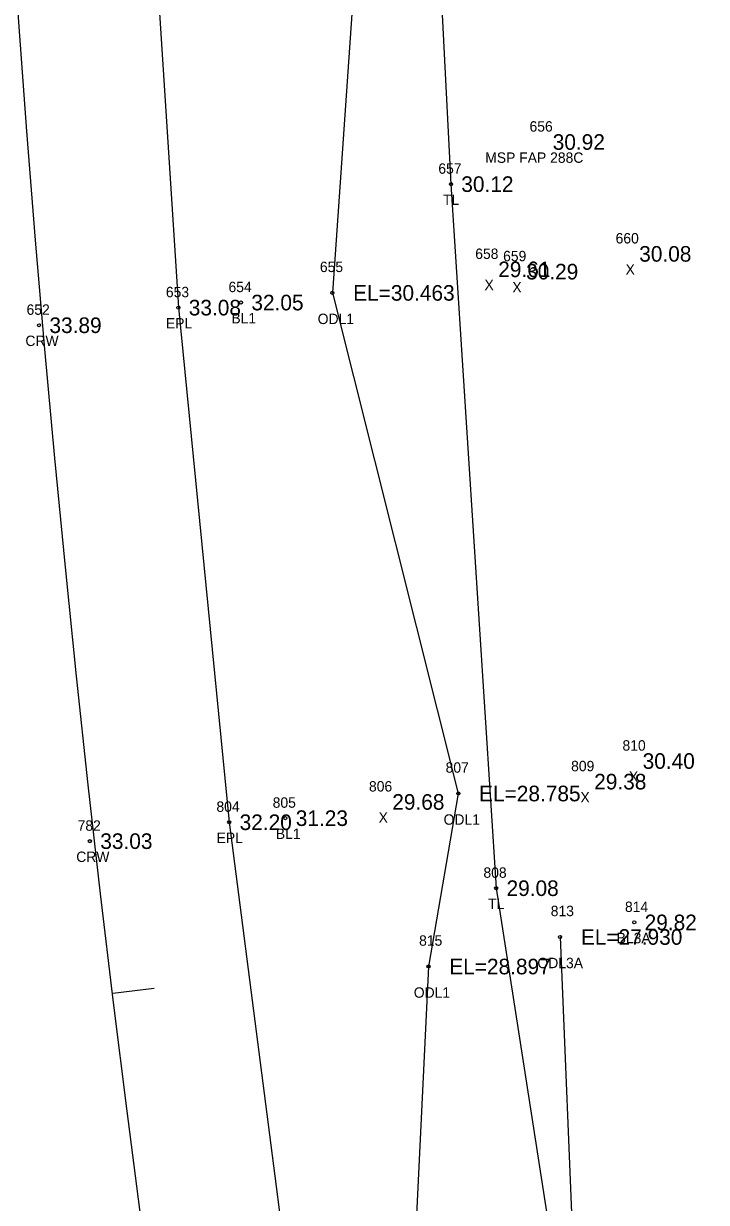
# Model space of a CAD drawing. Extents: x 2042117 to 2045853, y 303080 to 309569.
# Drawn here: x 2042845.4 to 2042911.1, y 307097.3 to 307210.7 of the extents above; entities that cross this region are included whole.
import ezdxf

# ---------------------------------------------------------------- set-up
doc = ezdxf.new("R2010")
doc.units = 0
for name, color, linetype in [('RD_DTM_BkLn_txCode', 7, 'Continuous'), ('RD_EX_H2O', 7, 'Continuous'), ('RD_EX_H2O_txCode', 7, 'Continuous'), ('RD_EX_Misc_txCode', 7, 'Continuous'), ('RD_EX_Road', 7, 'Continuous'), ('RD_EX_Road_txCode', 7, 'Continuous'), ('RD_EX_TX_H2O_ELEV', 7, 'Continuous'), ('RD_EX_TX_Misc_ELEV', 7, 'Continuous'), ('RD_EX_TX_Road_ELEV', 7, 'Continuous'), ('RD_EX_TX_VEG_ELEV', 7, 'Continuous'), ('RD_EX_VEG', 7, 'Continuous'), ('RD_EX_VEG_txCode', 7, 'Continuous'), ('RD_HC_Cl', 7, 'Continuous'), ('RD_HC_Data_Tic', 7, 'Continuous'), ('RD_HC_Survey_ELEV', 7, 'Continuous'), ('RD_HC_Survey_txCode', 7, 'Continuous'), ('RD_SMD_Locator', 7, 'Continuous')]:
    doc.layers.add(name, color=color, linetype=linetype)

msp = doc.modelspace()

# ---------------------------------------------------------------- linework, layer by layer
at = {"layer": 'RD_EX_H2O'}
for points in [[(2042865.43, 307427.05), (2042866.84, 307378.87), (2042866.82, 307329.93), (2042876.23, 307282.16), (2042878.43, 307232.86), (2042875.08, 307184.77), (2042887.19, 307136.65), (2042884.32, 307120.02), (2042882.74, 307087.49), (2042892.51, 307039.16), (2042896.41, 306990.42), (2042899.37, 306973.37), (2042910.05, 306942.23), (2042920.75, 306896.67), (2042927.15, 306846.78), (2042945.6, 306801.59), (2042960.32, 306754.61), (2042976.65, 306708.74), (2042994.63, 306662.76), (2043013.3, 306616.98), (2043029.17, 306571.91), (2043050.77, 306528.53)], [(2042896.98, 307122.86), (2042898.29, 307090.91), (2042908.74, 307042.51), (2042915.6, 306994.27), (2042923.33, 306977.91)]]:
    msp.add_lwpolyline(points, dxfattribs=at)
at = {"layer": 'RD_EX_Road'}
msp.add_lwpolyline([(2042855.03, 307427.78), (2042853.64, 307379.19), (2042853.31, 307329.44), (2042854.43, 307281.38), (2042857.15, 307232.07), (2042860.27, 307183.35), (2042865.16, 307133.89), (2042871.37, 307085.7), (2042878.53, 307037.13), (2042886.97, 306988.21), (2042897.02, 306940.01), (2042908.28, 306892.66), (2042921.09, 306844.85), (2042934.41, 306798.2)], dxfattribs=at)
at = {"layer": 'RD_EX_VEG'}
msp.add_lwpolyline([(2042885.61, 307482.85), (2042881.1, 307379.92), (2042880.44, 307351.7), (2042880.19, 307284.9), (2042884.99, 307224.08), (2042886.48, 307195.22), (2042890.83, 307127.55), (2042909.45, 307007.86), (2042916.1, 306960.95), (2042918.56, 306940.03), (2042926.66, 306909), (2042942.91, 306849.91), (2042954.33, 306802.72), (2042963.56, 306806.84), (2042974.33, 306847.25), (2043002.07, 306860.54), (2043032.14, 306846.51)], dxfattribs=at)
at = {"layer": 'RD_HC_Cl'}
msp.add_arc((2044751.25, 307348.43), 1911.29, 137.68184, 219.86836, dxfattribs=at)
at = {"layer": 'RD_HC_Data_Tic'}
msp.add_line((2042853.96, 307117.46), (2042857.93, 307117.94), dxfattribs=at)
at = {"layer": 'RD_SMD_Locator'}
for centre in [(2042886.48, 307195.22), (2042875.08, 307184.77), (2042860.27, 307183.35), (2042866.29, 307183.84), (2042846.87, 307181.66), (2042887.19, 307136.65), (2042865.16, 307133.89), (2042870.56, 307134.28), (2042851.76, 307132.07), (2042890.83, 307127.55), (2042904.11, 307124.26), (2042896.98, 307122.86), (2042884.32, 307120.02)]:
    msp.add_circle(centre, 0.15, dxfattribs=at)

# ---------------------------------------------------------------- texts
at = {"layer": 'RD_DTM_BkLn_txCode'}
for s, p in [('654', (2042865.09, 307184.84)), ('BL1', (2042865.37, 307181.84)), ('805', (2042869.34, 307135.28)), ('BL1', (2042869.64, 307132.28)), ('814', (2042903.22, 307125.26)), ('BL3A', (2042902.42, 307122.26))]:
    msp.add_text(s, height=1, dxfattribs=at).set_placement(p)
at = {"layer": 'RD_EX_H2O_txCode'}
for s, p in [('655', (2042873.88, 307186.77)), ('ODL1', (2042873.67, 307181.77)), ('807', (2042885.97, 307138.65)), ('ODL1', (2042885.78, 307133.65)), ('813', (2042896.08, 307124.86)), ('815', (2042883.42, 307122.02)), ('ODL3A', (2042894.8, 307119.86)), ('ODL1', (2042882.91, 307117.02))]:
    msp.add_text(s, height=1, dxfattribs=at).set_placement(p)
at = {"layer": 'RD_EX_Misc_txCode'}
for s, p in [('656', (2042894.04, 307200.27)), ('MSP FAP 288C', (2042889.78, 307197.27)), ('660', (2042902.32, 307189.52)), ('658', (2042888.82, 307188.03)), ('659', (2042891.5, 307187.81)), ('X', (2042903.28, 307186.52)), ('X', (2042889.71, 307185.03)), ('X', (2042892.39, 307184.81)), ('810', (2042902.98, 307140.77)), ('809', (2042898.04, 307138.79)), ('X', (2042903.6, 307137.77)), ('806', (2042878.6, 307136.84)), ('X', (2042898.94, 307135.79)), ('X', (2042879.53, 307133.84))]:
    msp.add_text(s, height=1, dxfattribs=at).set_placement(p)
at = {"layer": 'RD_EX_Road_txCode'}
for s, p in [('653', (2042859.07, 307184.35)), ('EPL', (2042859.07, 307181.35)), ('804', (2042863.93, 307134.89)), ('EPL', (2042863.95, 307131.89))]:
    msp.add_text(s, height=1, dxfattribs=at).set_placement(p)
at = {"layer": 'RD_EX_TX_H2O_ELEV'}
for s, p in [('EL=30.463', (2042877.08, 307184.02)), ('EL=28.785', (2042889.19, 307135.9)), ('EL=27.930', (2042898.98, 307122.11)), ('EL=28.897', (2042886.32, 307119.27))]:
    msp.add_text(s, height=1.5, dxfattribs=at).set_placement(p)
at = {"layer": 'RD_EX_TX_Misc_ELEV'}
for s, p in [('30.92', (2042896.27, 307198.52)), ('30.08', (2042904.59, 307187.77)), ('29.61', (2042891.03, 307186.28)), ('30.29', (2042893.71, 307186.06)), ('32.05', (2042867.29, 307183.09)), ('30.40', (2042904.92, 307139.02)), ('29.38', (2042900.26, 307137.04)), ('29.68', (2042880.84, 307135.09)), ('31.23', (2042871.56, 307133.53)), ('29.82', (2042905.11, 307123.51))]:
    msp.add_text(s, height=1.5, dxfattribs=at).set_placement(p)
at = {"layer": 'RD_EX_TX_Road_ELEV'}
for s, p in [('33.08', (2042861.27, 307182.6)), ('32.20', (2042866.16, 307133.14))]:
    msp.add_text(s, height=1.5, dxfattribs=at).set_placement(p)
at = {"layer": 'RD_EX_TX_VEG_ELEV'}
for s, p in [('30.12', (2042887.48, 307194.47)), ('29.08', (2042891.83, 307126.8))]:
    msp.add_text(s, height=1.5, dxfattribs=at).set_placement(p)
at = {"layer": 'RD_EX_VEG_txCode'}
for s, p in [('657', (2042885.27, 307196.22)), ('TL', (2042885.71, 307193.22)), ('808', (2042889.61, 307128.55)), ('TL', (2042890.06, 307125.55))]:
    msp.add_text(s, height=1, dxfattribs=at).set_placement(p)
at = {"layer": 'RD_HC_Survey_ELEV'}
for s, p in [('33.89', (2042847.87, 307180.91)), ('33.03', (2042852.76, 307131.32))]:
    msp.add_text(s, height=1.5, dxfattribs=at).set_placement(p)
at = {"layer": 'RD_HC_Survey_txCode'}
for s, p in [('652', (2042845.67, 307182.66)), ('CRW', (2042845.56, 307179.66)), ('782', (2042850.58, 307133.07)), ('CRW', (2042850.45, 307130.07))]:
    msp.add_text(s, height=1, dxfattribs=at).set_placement(p)

doc.saveas('drawing.dxf')
